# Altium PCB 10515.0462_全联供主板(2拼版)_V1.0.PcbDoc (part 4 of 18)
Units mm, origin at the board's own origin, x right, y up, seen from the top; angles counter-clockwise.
Board outline 282 x 198 mm, 2 copper layers (Top Layer, Bottom Layer); 716 components, 0 nets, 2364 pads, 1800 vias.
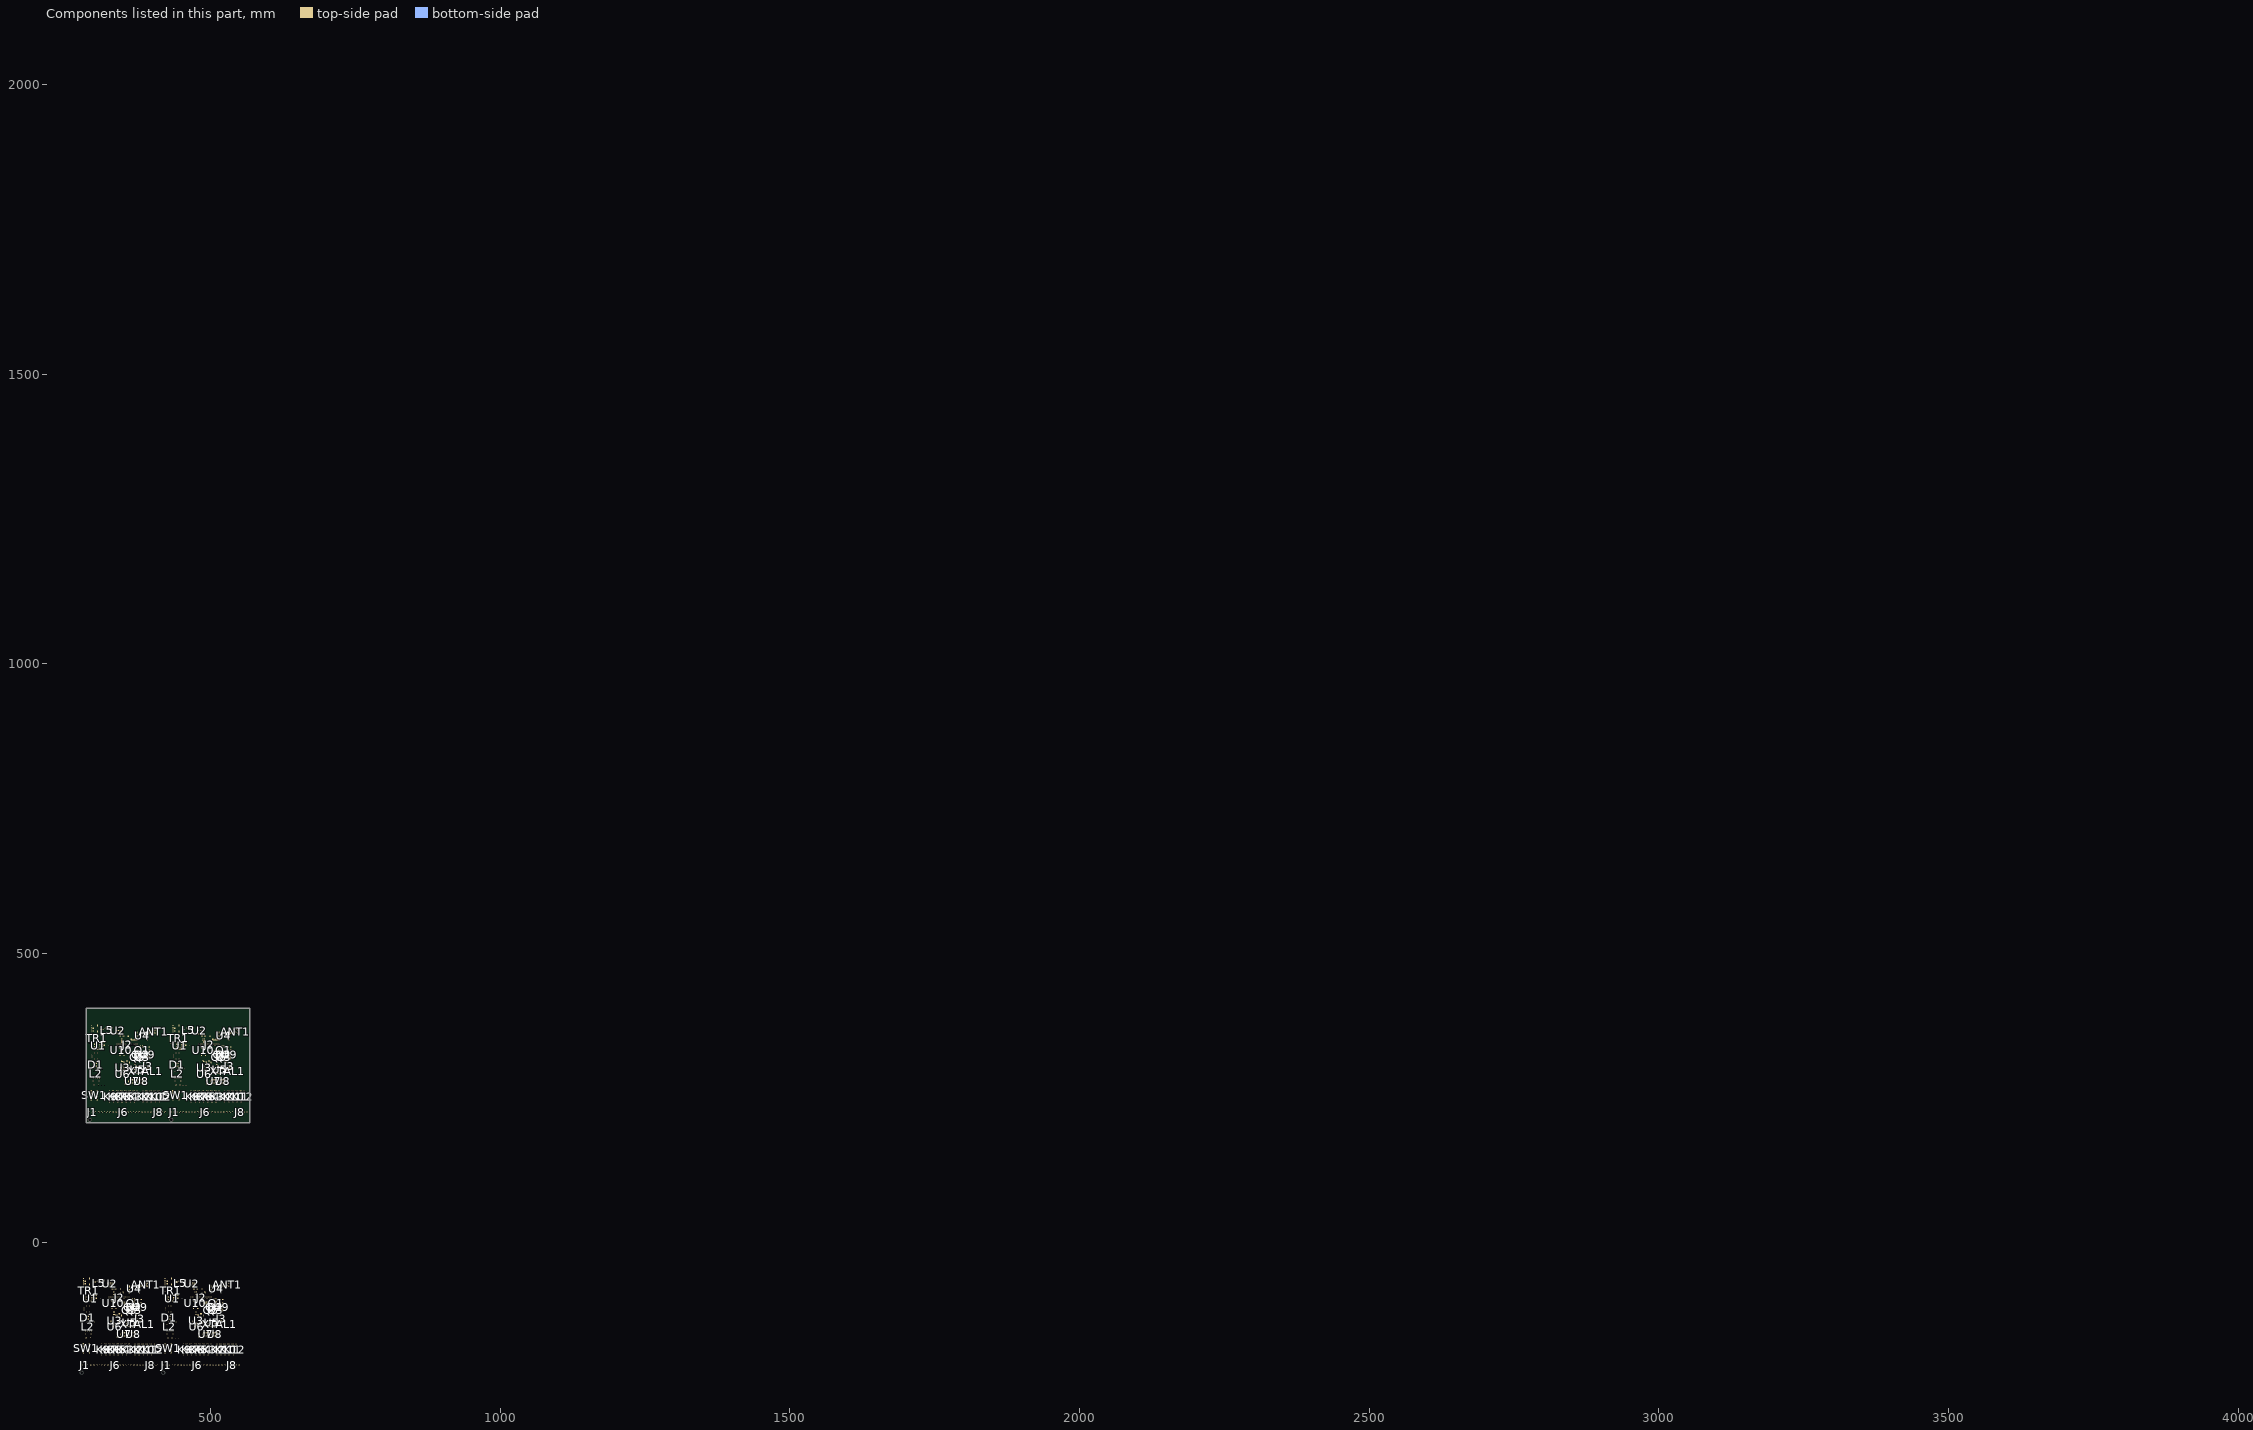
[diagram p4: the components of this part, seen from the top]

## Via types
v1: diameter 0.7, hole 0.4, Top Layer to Bottom Layer, tented both sides, 1800 vias

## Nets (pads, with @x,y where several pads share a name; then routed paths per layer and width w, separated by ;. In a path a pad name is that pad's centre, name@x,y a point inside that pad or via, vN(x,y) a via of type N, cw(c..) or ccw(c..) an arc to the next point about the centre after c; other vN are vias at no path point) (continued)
copper on no net: (continued)
  Top Layer w0.2: 384.544,295.781 ccw(c384.991,296.229) 384.991,295.596 ; 384.653,297.574 cw(c384.653,297.003) 385.057,297.407 ; 384.917,-74.482 385.033,-74.482 ; 385.228,311.309 cw(c384.705,310.786) 385.445,310.786 cw(c386.185,310.786) 385.662,311.309 ; 385.228,312.998 ccw(c384.705,312.475) 384.705,313.215 ccw(c384.705,313.955) 385.228,313.432 ; 385.297,295.69 cw(c385.792,295.69) 385.442,296.039 ; 385.437,322.933 cw(c384.697,322.194) 385.74,322.114 ; 385.629,320.162 cw(c385.106,319.639) 385.846,319.639 cw(c386.586,319.639) 386.063,320.162 ; 385.744,322.625 cw(c385.269,322.15) 385.939,322.099 ; 385.754,322.398 ccw(c385.714,322.523) 385.846,322.523 ccw(c385.978,322.523) 385.938,322.398 ; 386.411,301.303 387.841,301.303 ; 387.026,320.162 cw(c386.548,319.684) 387.224,319.684 ; 387.042,322.337 ccw(c386.66,322.777) 387.243,322.777 ccw(c387.826,322.777) 387.444,322.337 ; 387.224,319.594 cw(c388.028,319.594) 387.46,320.162 ; 387.587,301.086 ccw(c387.063,300.563) 387.063,301.303 ccw(c387.063,302.043) 387.587,301.52 ; 388.212,318.92 cw(c388.987,318.145) 389.077,319.238 ; 388.517,319.226 cw(c389.034,318.709) 389.094,319.437 ; 388.793,319.294 ccw(c388.674,319.258) 388.674,319.382 ; 388.793,319.471 cw(c388.674,319.507) 388.674,319.382 ; 388.819,295.758 ccw(c388.711,296.025) 388.999,296.025 ; v1@388.916,316.625 cw(c388.554,316.235) 389.086,316.235 ; 388.999,295.193 388.999,296.025 ; v1(389.086,316.808) 389.086,316.235 ; 389.086,319.382 388.673,319.382 ; 389.178,295.758 cw(c389.287,296.025) 388.999,296.025 ; v1@389.256,316.625 ccw(c389.618,316.235) 389.086,316.235 ; 389.53,301.341 389.492,301.303 391.277,301.303 ; 389.53,302.947 389.53,303.074 ; 389.656,348.23 cw(c392.417,348.23) 390.465,350.183 ; 389.656,348.713 cw(c391.935,348.713) 390.323,350.324 ; 389.656,349.196 cw(c391.452,349.196) 390.182,350.465 ; 389.656,349.678 cw(c390.969,349.678) 390.04,350.607 ; 389.747,301.086 cw(c390.27,300.563) 390.27,301.303 cw(c390.27,302.043) 389.747,301.52 ; 389.788,350.395 cw(c389.29,350.305) 389.648,349.948 cw(c389.986,349.609) 390.093,350.076 ; 389.833,352.27 ccw(c389.499,352.082) 389.499,352.465 ; 389.833,352.661 cw(c389.499,352.849) 389.499,352.465 ; 389.899,354.183 ccw(c389.216,353.5) 389.216,354.465 ccw(c389.216,355.431) 389.899,354.748 ; 389.899,356.183 ccw(c389.216,355.5) 389.216,356.465 ccw(c389.216,357.431) 389.899,356.748 ; 390.632,352.465 389.499,352.465 ; 390.632,354.465 389.213,354.465 388.767,354.019 388.767,347.288 388.132,346.653 352.572,346.653 352.11,346.191 352.11,345.175 ; 391.023,301.086 ccw(c390.499,300.563) 390.499,301.303 ccw(c390.499,302.043) 391.023,301.52 ; 391.312,302.838 391.312,302.897 391.312,303.024 ; 391.966,317.476 cw(c391.443,316.953) 392.183,316.953 cw(c392.923,316.953) 392.4,317.476 ; 392.183,317.731 392.183,316.415 391.815,316.046 389.275,316.046 389.086,316.235 ; 393.515,317.476 cw(c392.992,316.953) 393.731,316.953 cw(c394.471,316.953) 393.948,317.476 ; 394.558,303.251 ccw(c393.705,304.104) 394.912,304.104 ccw(c396.119,304.104) 395.265,303.251 ; 394.658,304.951 cw(c394.044,304.338) 394.912,304.338 ; 394.7,303.109 ccw(c394.188,303.621) 394.912,303.621 ccw(c395.636,303.621) 395.124,303.109 ; 394.912,303.024 394.912,305.078 ; 394.912,303.217 cw(c397.363,303.217) 395.63,304.951 ; 394.912,303.7 cw(c396.881,303.7) 395.488,305.092 ; 394.912,304.183 cw(c396.398,304.183) 395.347,305.234 ; 394.912,304.666 cw(c395.915,304.666) 395.206,305.375 ; 395.042,364.769 395.182,364.628 395.208,364.654 ; v1@396.046,362.114 v1@396.26,362.114 ; 398.546,362.114 398.661,362.114 ; 464.372,-67.652 464.436,-67.652 ; 464.712,-72.355 ccw(c464.616,-72.151) 464.841,-72.151 ; 464.801,-72.683 cw(c465.172,-72.444) 464.86,-72.132 ; 464.841,-72.632 464.841,-72.151 ; 464.969,-72.575 cw(c465.386,-72.307) 465.036,-71.957 ; 464.971,-72.355 cw(c465.066,-72.151) 464.841,-72.151 ; 465.137,-72.467 cw(c465.6,-72.17) 465.211,-71.781 ; 465.458,-70.292 466.105,-70.292 466.481,-70.668 466.481,-71.4 466.1,-71.781 465.211,-71.781 ; 465.458,-68.992 466.095,-68.992 ; 465.858,-70.392 cw(c465.858,-71.23) 466.451,-70.638 ; 465.858,-70.192 cw(c465.858,-70.547) 466.109,-70.296 ; 465.891,-68.898 ccw(c466.015,-68.549) 466.276,-68.811 ; 465.91,-70.378 cw(c466.045,-70.599) 466.229,-70.416 ; 465.929,-70.363 cw(c466.099,-70.534) 466.099,-70.292 cw(c466.099,-70.051) 465.929,-70.222 ; 465.93,-69.062 cw(c466.095,-69.223) 466.095,-68.992 ; 465.93,-68.922 ccw(c466.095,-68.762) 466.095,-68.992 ; 466.06,-67.869 cw(c465.537,-68.392) 466.277,-68.392 cw(c467.016,-68.392) 466.493,-67.869 ; 466.277,-67.652 466.277,-68.811 ; v1@467.024,-70.292 468.204,-70.292 ; v1@467.166,-70.434 cw(c467.508,-70.776) 467.508,-70.292 ; v1@467.166,-70.08 ccw(c467.678,-69.568) 467.678,-70.292 ; 467.239,-68.483 ccw(c466.408,-67.652) 467.583,-67.652 ; 467.58,-68.142 ccw(c467.09,-67.652) 467.783,-67.652 ; 467.674,-68.048 cw(c467.889,-68.263) 467.889,-67.959 ; 467.733,-70.363 ccw(c467.563,-70.534) 467.563,-70.292 ccw(c467.563,-70.051) 467.733,-70.222 ; 467.733,-69.713 ccw(c467.563,-69.884) 467.563,-69.642 ccw(c467.563,-69.401) 467.733,-69.572 ; 467.928,-67.652 467.928,-67.795 467.116,-68.606 467.116,-69.368 467.39,-69.642 468.204,-69.642 469.503,-69.642 470.519,-70.658 ; 468.243,-136.468 468.274,-136.499 ; 468.675,-69.713 cw(c468.845,-69.884) 468.845,-69.642 cw(c468.845,-69.401) 468.675,-69.572 ; 469.786,-134.848 469.817,-134.848 469.892,-134.923 ; 469.817,-136.499 470.123,-136.193 ; 469.974,-70.112 cw(c469.367,-70.718) 470.225,-70.718 ; 470.091,-70.23 ccw(c470.531,-69.79) 470.531,-70.412 ; 470.277,-68.852 470.412,-68.987 470.531,-69.106 ; 478,368.943 478.065,368.943 ; 478.34,364.241 ccw(c478.245,364.445) 478.47,364.445 ; 478.43,363.913 cw(c478.801,364.151) 478.489,364.463 ; 478.46,-146.854 483.91,-146.854 484.314,-146.449 484.314,-140.308 484.601,-140.021 490.899,-140.021 ; 478.46,-145.584 483.402,-145.584 483.914,-145.071 483.914,-142.393 ; 478.47,363.963 478.47,364.445 ; 478.598,364.021 cw(c479.015,364.289) 478.664,364.639 ; 478.6,364.241 cw(c478.695,364.445) 478.47,364.445 ; 478.766,364.129 cw(c479.228,364.426) 478.84,364.814 ; 479.087,366.303 479.734,366.303 480.11,365.927 480.11,365.195 479.729,364.814 478.84,364.814 478.47,364.445 ; 479.087,367.603 479.724,367.603 ; 479.481,-91.369 479.481,-91.42 ; 479.487,366.203 cw(c479.487,365.365) 480.079,365.958 ; 479.487,366.403 cw(c479.487,366.048) 479.738,366.299 ; 479.52,367.698 ccw(c479.643,368.047) 479.905,367.785 ; 479.539,366.218 cw(c479.674,365.996) 479.857,366.18 ; 479.557,366.233 cw(c479.728,366.062) 479.728,366.303 cw(c479.728,366.545) 479.557,366.374 ; 479.558,367.534 cw(c479.724,367.373) 479.724,367.603 ; 479.558,367.673 ccw(c479.724,367.834) 479.724,367.603 ; 479.57,-146.998 cw(c479.919,-147.348) 479.919,-146.854 cw(c479.919,-146.359) 479.57,-146.709 ; 479.57,-145.728 cw(c479.919,-146.078) 479.919,-145.584 cw(c479.919,-145.089) 479.57,-145.439 ; 479.689,368.727 cw(c479.166,368.204) 479.905,368.204 cw(c480.645,368.204) 480.122,368.727 ; 479.905,368.943 479.905,367.785 ; v1@480.075,-108.463 ccw(c479.621,-108.425) 479.943,-108.103 ; 480.128,-93.967 cw(c480.738,-94.576) 480.805,-93.717 ; v1@480.303,-108.235 cw(c480.265,-107.781) 479.943,-108.103 ; 480.31,-93.785 ccw(c480.043,-93.517) 480.421,-93.517 ; v1(480.324,-108.484) 479.943,-108.103 ; 480.538,-96.34 cw(c479.252,-97.627) 481.071,-97.627 ; v1@480.653,366.303 481.833,366.303 ; 480.68,-96.199 cw(c479.734,-97.144) 481.071,-97.144 ; v1@480.795,366.162 cw(c481.136,365.82) 481.136,366.303 ; v1@480.795,366.515 ccw(c481.306,367.027) 481.306,366.303 ; 480.821,-96.057 cw(c480.217,-96.661) 481.071,-96.661 ; 480.821,-95.795 481.071,-96.046 481.071,-108.469 481.428,-108.825 492.314,-108.825 492.903,-109.414 492.903,-126.264 492.914,-126.264 493.278,-126.629 498.609,-126.629 499.272,-127.291 499.272,-131.621 ; 480.821,-93.255 480.821,-93.274 479.943,-94.152 479.943,-108.103 ; 480.867,368.112 ccw(c480.036,368.943) 481.212,368.943 ; 480.918,-134.923 480.993,-134.848 ; 481.209,368.454 ccw(c480.719,368.943) 481.412,368.943 ; 481.303,368.548 cw(c481.518,368.333) 481.518,368.637 ; 481.362,366.233 ccw(c481.191,366.062) 481.191,366.303 ccw(c481.191,366.545) 481.362,366.374 ; 481.362,366.883 ccw(c481.191,366.712) 481.191,366.953 ccw(c481.191,367.195) 481.362,367.024 ; v1@481.544,-107.545 ccw(c481.118,-107.118) 481.721,-107.118 ccw(c482.325,-107.118) v1@481.898,-107.545 ; 481.556,368.943 481.556,368.801 480.745,367.989 480.745,367.227 481.019,366.953 481.833,366.953 483.132,366.953 484.148,365.938 ; v1(481.721,-110.389) 481.721,-110.77 ; v1(481.721,-107.722) 481.721,-90.958 482.337,-90.342 515.865,-90.342 516.538,-89.669 516.538,-84.462 516.87,-84.13 ; 481.872,300.128 481.903,300.097 ; 482.303,366.883 cw(c482.474,366.712) 482.474,366.953 cw(c482.474,367.195) 482.303,367.024 ; v1@482.36,-107.214 ccw(c481.757,-107.214) 482.183,-106.787 ccw(c482.61,-106.36) v1@482.61,-106.964 ; v1(482.61,-107.214) 482.121,-106.725 482.121,-92.101 482.121,-91.339 482.718,-90.742 516.354,-90.742 517.027,-90.069 517.027,-86.64 517.537,-86.13 518.003,-86.13 ; v1(482.737,-110.389) 482.864,-110.262 491.269,-110.262 491.703,-110.697 491.703,-132.646 491.701,-132.648 491.701,-133.85 491.703,-133.852 491.703,-134.573 492.152,-135.021 495.372,-135.021 ; v1@482.772,-110.424 cw(c483.164,-110.816) 483.164,-110.262 ; v1@482.914,-110.566 cw(c483.647,-111.299) 483.647,-110.262 ; 483.078,-96.34 cw(c482.395,-97.023) 483.361,-97.023 cw(c484.327,-97.023) 483.644,-96.34 ; v1@483.122,-91.593 cw(c482.519,-91.593) 482.945,-92.02 cw(c483.372,-92.447) v1@483.372,-91.843 ; v1@483.195,-107.545 ccw(c482.769,-107.118) 483.372,-107.118 ccw(c483.976,-107.118) v1@483.549,-107.545 ; 483.361,-95.795 483.361,-106.314 484.022,-106.975 484.022,-107.864 484.584,-108.425 492.966,-108.425 493.303,-108.763 493.303,-125.756 493.684,-126.137 498.999,-126.137 499.772,-126.91 499.772,-131.621 ; 483.361,-93.255 484.161,-94.055 484.161,-106.467 484.422,-106.728 484.422,-107.698 484.749,-108.025 493.131,-108.025 493.703,-108.597 493.703,-125.292 494.04,-125.629 499.499,-125.629 500.272,-126.402 500.272,-131.621 ; v1(483.372,-107.722) 483.372,-106.96 482.521,-106.109 482.521,-92.444 v1(483.372,-91.593) ; 483.395,-93.715 cw(c483.515,-94.417) 484.019,-93.913 ; 483.415,301.748 483.446,301.748 483.52,301.673 ; 483.446,300.097 483.752,300.403 ; 483.602,366.483 cw(c482.996,365.877) 483.853,365.877 ; 483.72,366.366 ccw(c484.16,366.806) 484.16,366.183 ; v1@483.753,-112.036 cw(c483.753,-112.64) 484.18,-112.213 cw(c484.607,-111.786) v1@484.003,-111.786 ; v1(483.753,-111.786) 484.403,-112.436 485.658,-112.436 485.908,-112.186 490.249,-112.186 490.503,-112.44 490.503,-132.149 490.501,-132.151 490.501,-134.347 490.503,-134.349 490.503,-135.139 491.886,-136.521 495.372,-136.521 ; 483.761,-93.517 ccw(c484.094,-93.517) 483.859,-93.753 ; 483.906,367.744 484.041,367.608 484.16,367.49 ; 483.914,-141.134 483.914,-142.393 ; v1@484.465,-92.278 cw(c484.039,-92.705) 484.642,-92.705 cw(c485.246,-92.705) v1@484.819,-92.278 ; v1(484.642,-92.101) 484.642,-106.383 485.101,-106.842 ; v1@484.973,-107.164 ccw(c484.665,-106.856) 485.101,-106.856 ; v1(485.023,-111.786) 490.738,-111.786 490.903,-111.951 490.903,-132.315 490.901,-132.317 490.901,-134.181 490.903,-134.183 490.903,-134.973 491.951,-136.021 495.372,-136.021 ; v1(485.15,-107.341) 485.101,-107.292 485.101,-106.842 ; v1@485.2,-111.963 cw(c485.627,-112.39) 485.627,-111.786 cw(c485.627,-111.182) v1@485.2,-111.609 ; 485.212,-93.944 cw(c485.778,-94.51) 485.876,-93.716 ; v1@485.268,-107.121 cw(c485.417,-106.842) 485.101,-106.842 ; 485.403,-93.753 ccw(c485.168,-93.517) 485.501,-93.517 ; 485.617,-136.435 485.642,-136.461 ; 485.618,-96.34 cw(c484.935,-97.023) 485.901,-97.023 cw(c486.867,-97.023) 486.184,-96.34 ; 485.901,-95.795 485.901,-106.441 486.686,-107.225 494.179,-107.225 494.503,-107.55 494.503,-124.403 494.929,-124.829 500.461,-124.829 501.272,-125.64 501.272,-131.621 ; 485.901,-93.255 485.054,-94.103 485.054,-106.228 486.451,-107.625 493.69,-107.625 494.103,-108.039 494.103,-124.911 494.421,-125.229 499.98,-125.229 500.772,-126.021 500.772,-131.621 ; v1@486.293,-112.929 v1(486.547,-112.929) 489.468,-112.929 490.103,-113.564 490.103,-131.984 490.101,-131.986 490.101,-134.512 490.103,-134.514 490.103,-135.386 491.739,-137.021 495.372,-137.021 ; v1@486.678,-106.452 ccw(c486.075,-106.452) 486.501,-106.025 ccw(c486.928,-105.598) v1@486.928,-106.202 ; v1@486.724,-113.106 cw(c487.151,-113.533) 487.151,-112.929 cw(c487.151,-112.325) v1@486.724,-112.752 ; v1@486.751,-92.278 cw(c486.325,-92.705) 486.928,-92.705 cw(c487.532,-92.705) v1@487.105,-92.278 ; v1(486.928,-106.452) 486.42,-105.944 486.42,-97.17 486.928,-96.662 v1(486.928,-92.101) ; 487.102,-136.461 487.127,-136.461 ; 487.187,-138.115 cw(c486.504,-138.798) 487.47,-138.798 cw(c488.436,-138.798) 487.753,-138.115 ; 487.47,-137.832 487.47,-138.848 487.654,-139.032 495.361,-139.032 495.372,-139.021 ; 488.436,-153.924 ccw(c488.009,-153.497) 488.613,-153.497 ccw(c489.217,-153.497) 488.79,-153.924 ; 488.507,-136.097 488.833,-136.424 490.507,-136.424 491.604,-137.521 495.372,-137.521 ; 488.613,-154.85 488.613,-150.278 489.267,-149.624 497.757,-149.624 498.272,-149.109 498.272,-143.921 ; 488.897,-105.537 cw(c488.374,-106.06) 489.114,-106.06 cw(c489.854,-106.06) 489.331,-105.537 ; 488.994,-137.832 488.994,-138.285 489.341,-138.632 494.118,-138.632 494.229,-138.521 495.372,-138.521 ; 489.058,-136.652 cw(c489.609,-137.203) 489.609,-136.424 ; 489.058,-136.219 ccw(c489.554,-135.723) 489.554,-136.424 ; 489.114,-105.32 489.114,-106.471 489.468,-106.825 494.515,-106.825 494.903,-107.214 494.903,-124.105 495.227,-124.429 501.069,-124.429 501.772,-125.132 501.772,-131.621 ; 489.114,-103.669 v1@489.756,-103.669 ; 489.399,-103.85 cw(c489.756,-104.111) v1@489.756,-103.669 ; 489.399,-103.489 ccw(c489.756,-103.228) v1@489.756,-103.669 ; 489.706,-153.924 ccw(c489.279,-153.497) 489.883,-153.497 ccw(c490.487,-153.497) 490.06,-153.924 ; v1@489.706,-103.846 ccw(c489.279,-104.273) 489.279,-103.669 ccw(c489.279,-103.066) v1@489.706,-103.493 ; 489.883,-154.85 489.883,-150.786 490.645,-150.024 498.138,-150.024 498.772,-149.39 498.772,-143.921 ; 490.682,-141.238 ccw(c490.159,-140.715) 490.899,-140.715 ccw(c491.639,-140.715) 491.116,-141.238 ; 490.707,-138.021 495.372,-138.021 ; 490.899,-141.492 490.899,-140.021 ; 490.976,-153.924 ccw(c490.549,-153.497) 491.153,-153.497 ccw(c491.757,-153.497) 491.33,-153.924 ; 491.153,-154.85 491.153,-151.167 491.845,-150.475 498.703,-150.475 499.272,-149.906 499.272,-143.921 ; 492.089,289.742 497.539,289.742 497.943,290.146 497.943,296.287 498.229,296.574 504.528,296.574 ; 492.089,291.012 497.031,291.012 497.543,291.524 497.543,294.202 ; 492.246,-153.924 ccw(c491.819,-153.497) 492.423,-153.497 ccw(c493.027,-153.497) 492.6,-153.924 ; 492.423,-154.85 492.423,-151.421 492.969,-150.875 499.192,-150.875 499.772,-150.295 499.772,-143.921 ; 492.46,-105.537 cw(c491.937,-106.06) 492.677,-106.06 cw(c493.417,-106.06) 492.894,-105.537 ; 492.632,-101.941 v1@493.262,-101.941 ; 492.657,-141.49 492.727,-141.49 ; 492.677,-105.32 492.677,-106.078 493.024,-106.425 495.03,-106.425 495.303,-106.699 495.303,-123.724 495.303,-123.768 495.564,-124.029 501.55,-124.029 502.272,-124.751 502.272,-131.621 ; 492.677,-103.669 v1(493.439,-103.669) ; 492.727,-143.141 493.464,-143.141 ; 492.92,-102.118 cw(c493.262,-102.36) v1@493.262,-101.941 ; 492.92,-101.765 ccw(c493.262,-101.523) v1@493.262,-101.941 ; 492.935,-103.883 cw(c493.439,-104.371) v1(493.439,-103.669) ; 492.935,-103.456 ccw(c493.439,-102.968) v1(493.439,-103.669) ; 492.944,-143.357 cw(c493.464,-143.875) 493.464,-143.141 ; 492.944,-142.925 ccw(c493.464,-142.407) 493.464,-143.141 ; 493.11,345.226 493.11,345.175 ; 493.199,289.597 cw(c493.548,289.247) 493.548,289.742 cw(c493.548,290.236) 493.199,289.887 ; 493.199,290.867 cw(c493.548,290.517) 493.548,291.012 cw(c493.548,291.506) 493.199,291.157 ; v1@493.212,-102.118 ccw(c492.785,-102.545) 492.785,-101.941 ccw(c492.785,-101.338) v1@493.212,-101.765 ; v1@493.262,-103.846 ccw(c492.835,-104.273) 492.835,-103.669 ccw(c492.835,-103.066) v1@493.262,-103.493 ; 493.516,-153.924 ccw(c493.089,-153.497) 493.693,-153.497 ccw(c494.297,-153.497) 493.87,-153.924 ; 493.521,-93.917 cw(c493.521,-95.516) 494.651,-94.386 cw(c495.781,-93.255) 494.183,-93.255 ; 493.521,-93.717 cw(c493.521,-94.833) 494.31,-94.044 cw(c495.098,-93.255) 493.983,-93.255 ; 493.521,-93.255 494.802,-94.537 494.802,-98.324 495.075,-98.597 498.485,-98.597 498.823,-98.935 498.823,-99.805 499.12,-100.102 512.328,-100.102 512.709,-100.483 512.709,-113.564 513.217,-114.072 ; 493.693,-154.85 493.693,-151.929 494.347,-151.275 499.554,-151.275 500.272,-150.557 500.272,-143.921 ; v1@493.704,328.132 ccw(c493.25,328.17) 493.572,328.492 ccw(c493.894,328.815) v1@493.932,328.361 ; 493.757,342.629 cw(c494.367,342.019) 494.434,342.879 ; v1@493.786,-81.56 496.834,-81.56 497.45,-81.56 497.704,-81.306 497.704,-72.784 498.358,-72.13 500.303,-72.13 ; v1@493.913,-141.021 495.372,-141.021 ; 493.939,342.811 ccw(c493.672,343.078) 494.05,343.078 ; v1(493.953,328.111) 493.572,328.492 493.572,342.443 494.45,343.321 494.45,343.34 ; 494.167,340.255 cw(c492.88,338.969) 494.7,338.969 ; v1(494.294,-82.322) 494.548,-82.068 496.58,-82.068 497.85,-82.068 498.104,-81.814 498.104,-81.179 498.104,-74.575 498.549,-74.13 500.303,-74.13 ; 494.308,340.397 cw(c493.363,339.451) 494.7,339.451 ; 494.389,-141.663 cw(c494.707,-141.981) 494.707,-141.531 ; 494.443,-141.61 cw(c494.646,-141.813) 494.705,-141.531 ; 494.45,340.538 cw(c493.846,339.934) 494.7,339.934 ; 494.45,340.8 494.7,340.55 494.7,328.126 495.056,327.77 505.943,327.77 506.532,327.181 506.532,310.331 506.542,310.331 506.907,309.967 512.238,309.967 512.901,309.304 512.901,304.974 ; 494.547,301.673 494.622,301.748 ; 494.786,-153.924 ccw(c494.359,-153.497) 494.963,-153.497 ccw(c495.567,-153.497) 495.14,-153.924 ; v1@494.929,-82.957 497.469,-82.957 498.358,-82.957 498.612,-82.703 498.612,-80.384 498.866,-80.13 ; 494.963,-154.85 494.963,-152.183 495.471,-151.675 500.043,-151.675 500.772,-150.946 500.772,-143.921 ; v1@495.106,-83.134 cw(c495.533,-83.561) 495.533,-82.957 cw(c495.533,-82.353) v1@495.106,-82.78 ; v1@495.173,329.05 ccw(c494.746,329.477) 495.35,329.477 ccw(c495.953,329.477) v1@495.527,329.05 ; v1(495.35,326.206) 495.35,325.825 ; v1(495.35,328.873) 495.35,345.637 495.966,346.253 529.494,346.253 530.167,346.926 530.167,352.133 530.499,352.465 ; 495.372,-141.521 494.531,-141.521 493.82,-142.232 493.82,-142.785 493.464,-143.141 ; 495.372,-140.521 504.768,-140.521 505.055,-140.234 505.055,-133.41 505.993,-132.472 506.979,-132.472 v1(507.629,-133.122) ; 495.372,-140.021 490.899,-140.021 ; 495.372,-139.521 484.212,-139.521 483.914,-139.819 483.914,-142.393 ; 495.372,-135.521 492.017,-135.521 491.303,-134.808 491.303,-134.017 491.301,-134.015 491.301,-132.483 491.303,-132.481 491.303,-111.211 491.117,-111.024 483.021,-111.024 483.006,-111.039 481.99,-111.039 481.721,-110.77 ; 495.372,-134.521 492.414,-134.521 492.103,-134.211 492.103,-133.686 492.101,-133.684 492.101,-132.814 492.103,-132.812 492.103,-110.322 491.407,-109.625 479.63,-109.625 479.081,-109.077 479.081,-89.915 479.562,-89.434 515.122,-89.434 515.63,-88.926 515.63,-80.798 516.298,-80.13 518.003,-80.13 ; 495.372,-134.021 492.781,-134.021 492.503,-133.744 492.503,-133.52 492.501,-133.518 492.501,-132.98 492.503,-132.978 492.503,-109.814 491.915,-109.225 479.796,-109.225 479.481,-108.911 479.481,-91.42 ; 495.593,-96.264 cw(c494.463,-97.394) 496.061,-97.394 cw(c497.659,-97.394) 496.529,-96.264 ; 495.734,-96.122 cw(c494.946,-96.911) 496.061,-96.911 cw(c497.176,-96.911) 496.388,-96.122 ; 495.882,-105.537 cw(c495.359,-106.06) 496.099,-106.06 cw(c496.839,-106.06) 496.316,-105.537 ; 495.915,-129.971 cw(c495.392,-130.494) 496.131,-130.494 cw(c496.871,-130.494) 496.348,-129.971 ; v1@495.989,329.381 ccw(c495.385,329.381) 495.812,329.808 ccw(c496.239,330.235) v1@496.239,329.631 ; 496.056,-153.924 ccw(c495.629,-153.497) 496.233,-153.497 ccw(c496.837,-153.497) 496.41,-153.924 ; 496.061,-95.795 496.061,-97.932 496.326,-98.197 498.745,-98.197 499.227,-98.679 499.227,-99.428 499.501,-99.702 512.69,-99.702 513.109,-100.121 513.109,-100.864 513.109,-113.202 513.344,-113.437 514.233,-113.437 514.614,-113.818 ; 496.061,-93.917 cw(c496.061,-95.516) 497.191,-94.386 cw(c498.321,-93.255) 496.723,-93.255 ; 496.061,-93.717 cw(c496.061,-94.833) 496.85,-94.044 cw(c497.638,-93.255) 496.523,-93.255 ; 496.061,-93.255 497.215,-94.41 497.215,-97.543 497.469,-97.797 498.911,-97.797 499.311,-98.197 505.871,-98.197 ; 496.099,-105.32 496.099,-106.298 495.703,-106.694 495.703,-123.216 495.703,-123.26 496.072,-123.629 501.819,-123.629 502.772,-124.582 502.772,-131.621 ; 496.099,-103.669 496.443,-103.669 496.106,-103.669 ; 496.131,-129.754 496.131,-130.514 496.453,-130.836 497.596,-130.836 ; 496.233,-154.85 496.233,-152.818 496.868,-152.183 500.297,-152.183 501.272,-151.208 501.272,-143.921 ; v1(496.239,329.381) 495.75,329.87 495.75,344.494 495.75,345.256 496.347,345.853 529.983,345.853 530.656,346.526 530.656,349.955 531.166,350.465 531.632,350.465 ; 496.324,-114.27 ccw(c495.778,-113.724) 496.551,-113.724 ; 496.334,-112.96 cw(c495.811,-113.483) 496.551,-113.483 cw(c497.29,-113.483) 496.767,-112.96 ; v1(496.366,326.206) 496.493,326.333 504.897,326.333 505.332,325.899 505.332,303.949 505.33,303.947 505.33,302.746 505.332,302.744 505.332,302.023 505.781,301.574 509.001,301.574 ; v1@496.401,326.171 cw(c496.793,325.779) 496.793,326.333 ; v1@496.543,326.03 cw(c497.276,325.296) 497.276,326.333 ; 496.551,-114.439 496.551,-112.743 ; 496.551,-113.77 ccw(c497.258,-113.77) 496.758,-114.27 ; 496.707,340.255 cw(c496.024,339.572) 496.99,339.572 cw(c497.955,339.572) 497.273,340.255 ; v1@496.751,345.002 cw(c496.147,345.002) 496.574,344.576 cw(c497.001,344.149) v1@497.001,344.752 ; v1@496.824,329.05 ccw(c496.397,329.477) 497.001,329.477 ccw(c497.604,329.477) v1@497.178,329.05 ; 496.99,340.8 496.99,330.282 497.651,329.62 497.651,328.731 498.212,328.17 506.594,328.17 506.932,327.832 506.932,310.839 507.313,310.458 512.627,310.458 513.401,309.685 513.401,304.974 ; 496.99,343.34 497.79,342.54 497.79,330.128 498.051,329.867 498.051,328.897 498.378,328.57 506.76,328.57 507.332,327.998 507.332,311.303 507.669,310.966 513.127,310.966 513.901,310.193 513.901,304.974 ; v1(497.001,328.873) 497.001,329.635 496.15,330.486 496.15,344.151 v1(497.001,345.002) ; 497.024,342.881 cw(c497.144,342.179) 497.647,342.682 ; v1@497.382,324.559 cw(c497.382,323.956) 497.809,324.383 cw(c498.235,324.809) v1@497.632,324.809 ; v1(497.382,324.809) 498.032,324.159 499.287,324.159 499.537,324.409 503.878,324.409 504.132,324.155 504.132,304.446 504.13,304.444 504.13,302.249 504.132,302.247 504.132,301.457 505.514,300.074 509.001,300.074 ; 497.39,343.078 ccw(c497.723,343.078) 497.487,342.842 ; 497.457,-130.836 cw(c497.457,-131.271) 497.765,-130.963 ; 497.543,295.461 497.543,294.202 ; 497.66,-130.9 ccw(c497.772,-130.788) 497.772,-130.946 ; 497.762,-130.959 ccw(c497.596,-131.01) 497.596,-130.836 ; 497.772,-143.921 497.772,-141.963 498.104,-141.631 504.835,-141.631 505.455,-141.011 505.455,-133.645 505.978,-133.122 v1(506.613,-133.122) ; 497.772,-131.621 497.772,-131.012 497.596,-130.836 ; 497.782,-129.754 498.272,-130.244 498.272,-131.621 ; 497.833,-130.061 cw(c497.855,-130.623) 498.253,-130.225 cw(c498.587,-129.891) 498.122,-129.808 ; 497.985,-116.474 cw(c497.462,-116.997) 498.202,-116.997 cw(c498.941,-116.997) 498.418,-116.474 ; v1@498.094,344.318 cw(c497.667,343.891) 498.271,343.891 cw(c498.874,343.891) v1@498.448,344.318 ; 498.202,-116.257 498.202,-120.243 498.202,-122.818 498.599,-123.216 502.93,-123.216 503.272,-123.558 503.272,-131.621 ; v1(498.271,344.494) 498.271,330.213 498.73,329.754 ; 498.601,-95.795 498.601,-96.916 498.866,-97.181 502.422,-97.181 503.946,-95.657 505.871,-95.657 ; 498.601,-93.917 cw(c498.601,-95.516) 499.731,-94.386 cw(c500.861,-93.255) 499.263,-93.255 ; 498.601,-93.717 cw(c498.601,-94.833) 499.39,-94.044 cw(c500.178,-93.255) 499.063,-93.255 ; 498.601,-93.255 499.86,-94.514 501.857,-94.514 502.619,-93.752 524.52,-93.752 525.047,-94.279 525.047,-144.533 524.412,-145.168 511.224,-145.168 510.692,-144.636 510.692,-141.115 510.098,-140.521 507.672,-140.521 ; v1@498.602,329.431 ccw(c498.294,329.739) 498.73,329.739 ; v1(498.652,324.809) 504.367,324.809 504.532,324.644 504.532,304.28 504.53,304.278 504.53,302.415 504.532,302.413 504.532,301.622 505.58,300.574 509.001,300.574 ; v1(498.779,329.254) 498.73,329.304 498.73,329.754 ; v1@498.829,324.633 cw(c499.255,324.206) 499.255,324.809 cw(c499.255,325.413) v1@498.829,324.986 ; 498.841,342.651 cw(c499.407,342.085) 499.505,342.88 ; v1@498.897,329.475 cw(c499.046,329.754) 498.73,329.754 ; 499.032,342.842 ccw(c498.797,343.078) 499.13,343.078 ; 499.245,300.16 499.271,300.135 ; 499.247,340.255 cw(c498.564,339.572) 499.53,339.572 cw(c500.495,339.572) 499.813,340.255 ; 499.53,340.8 499.53,330.155 500.314,329.37 507.807,329.37 508.132,329.045 508.132,312.192 508.558,311.766 514.089,311.766 514.901,310.955 514.901,304.974 ; 499.53,343.34 498.682,342.493 498.682,330.367 500.079,328.97 507.318,328.97 507.732,328.556 507.732,311.684 508.05,311.366 513.608,311.366 514.401,310.574 514.401,304.974 ; 499.57,-80.413 ccw(c498.887,-81.096) 498.887,-80.13 ; 499.57,-79.847 cw(c498.887,-79.164) 498.887,-80.13 ; 499.57,-74.413 ccw(c498.887,-75.096) 498.887,-74.13 ccw(c498.887,-73.164) 499.57,-73.847 ; 499.57,-72.413 ccw(c498.887,-73.096) 498.887,-72.13 ccw(c498.887,-71.164) 499.57,-71.847 ; 499.89,-119.126 cw(c499.367,-119.649) 500.107,-119.649 cw(c500.846,-119.649) 500.323,-119.126 ; v1@499.922,323.666 v1(500.176,323.666) 503.097,323.666 503.732,323.031 503.732,304.612 503.73,304.61 503.73,302.083 503.732,302.081 503.732,301.21 505.368,299.574 509.001,299.574 ; 500.107,-118.909 500.107,-121.154 500.263,-121.311 507.629,-121.311 507.968,-121.65 507.968,-131.177 507.524,-131.621 505.272,-131.621 ; 500.303,-80.13 498.887,-80.13 ; v1@500.307,330.143 ccw(c499.703,330.143) 500.13,330.57 ccw(c500.557,330.997) v1@500.557,330.393 ; v1@500.353,323.49 cw(c500.779,323.063) 500.779,323.666 cw(c500.779,324.27) v1@500.353,323.843 ; v1@500.38,344.318 cw(c499.953,343.891) 500.557,343.891 cw(c501.16,343.891) v1@500.734,344.318 ; v1(500.557,330.143) 500.049,330.651 500.049,339.426 500.557,339.934 v1(500.557,344.494) ; 500.73,300.135 500.756,300.135 ; 500.816,298.48 cw(c500.133,297.797) 501.099,297.797 cw(c502.064,297.797) 501.382,298.48 ; 501.099,298.763 501.099,297.747 501.283,297.563 508.99,297.563 509.001,297.574 ; 501.141,-93.255 525.04,-93.255 525.447,-93.663 525.447,-144.768 524.647,-145.568 511.058,-145.568 510.203,-144.713 510.203,-141.388 509.836,-141.021 507.672,-141.021 ; 501.313,-95.623 501.141,-95.795 502.784,-94.152 524.158,-94.152 524.647,-94.641 524.647,-144.367 524.246,-144.768 511.389,-144.768 511.092,-144.471 511.092,-140.753 510.36,-140.021 507.672,-140.021 ; 501.468,-93.582 cw(c502.256,-94.371) 502.256,-93.255 cw(c502.256,-92.14) 501.468,-92.929 ; 501.609,-93.724 cw(c502.739,-94.854) 502.739,-93.255 cw(c502.739,-91.657) 501.609,-92.787 ; 501.758,-109.765 501.782,-109.79 ; 501.772,-143.921 501.772,-151.649 502.587,-152.464 503.753,-152.464 503.98,-152.691 503.98,-154.85 ; 501.78,-114.423 501.948,-114.591 ; 501.78,-112.803 501.782,-112.801 ; 502.065,282.672 ccw(c501.638,283.099) 502.242,283.099 ccw(c502.845,283.099) 502.419,282.672 ; 502.135,300.498 502.462,300.171 504.135,300.171 505.233,299.074 509.001,299.074 ; 502.242,281.745 502.242,286.317 502.896,286.971 511.386,286.971 511.901,287.486 511.901,292.674 ; 502.272,-143.921 502.272,-151.387 502.949,-152.064 504.877,-152.064 505.25,-152.437 505.25,-154.85 ; 502.526,331.058 cw(c502.003,330.535) 502.743,330.535 cw(c503.483,330.535) 502.96,331.058 ; 502.623,298.763 502.623,298.31 502.97,297.963 507.746,297.963 507.857,298.074 509.001,298.074 ; 502.687,299.943 cw(c503.238,299.393) 503.238,300.171 ; 502.687,300.377 ccw(c503.183,300.872) 503.183,300.171 ; 502.743,331.275 502.743,330.124 503.097,329.77 508.143,329.77 508.532,329.381 508.532,312.49 508.856,312.166 514.697,312.166 515.401,311.463 515.401,304.974 ; 502.743,332.926 v1@503.385,332.926 ; 502.772,-143.921 502.772,-150.998 503.438,-151.664 506.255,-151.664 506.52,-151.929 506.52,-154.85 ; 503.028,332.745 cw(c503.385,332.484) v1@503.385,332.926 ; 503.028,333.107 ccw(c503.385,333.368) v1@503.385,332.926 ; 503.272,-143.921 503.272,-147.357 503.853,-147.938 503.853,-148.31 ; 503.335,282.672 ccw(c502.908,283.099) 503.512,283.099 ccw(c504.115,283.099) 503.689,282.672 ; v1@503.335,332.749 ccw(c502.908,332.323) 502.908,332.926 ccw(c502.908,333.53) v1@503.335,333.103 ; 503.443,-147.528 cw(c502.709,-148.262) 503.747,-148.271 ; v1@503.502,-122.25 cw(c502.851,-122.901) 503.772,-122.901 ; 503.512,281.745 503.512,285.809 504.274,286.571 511.767,286.571 512.401,287.205 512.401,292.674 ; v1@503.644,-122.108 cw(c503.334,-122.418) 503.772,-122.418 ; 503.772,-143.921 503.772,-147.149 504.107,-147.484 504.869,-147.484 505.123,-147.738 505.123,-150.856 505.377,-151.11 507.479,-151.11 507.79,-151.421 507.79,-154.85 ; 503.772,-131.621 v1@503.772,-122.166 ; 503.772,-122.452 cw(c504.058,-122.452) v1@503.856,-122.25 ; 503.772,-116.75 503.772,-116.641 ; 503.78,-147.865 cw(c503.378,-148.268) 503.947,-148.273 ; 503.803,-153.924 ccw(c503.376,-153.497) 503.98,-153.497 ccw(c504.584,-153.497) 504.157,-153.924 ; 504.272,-143.921 504.272,-146.868 504.488,-147.084 505.035,-147.084 505.523,-147.573 505.523,-150.475 505.758,-150.71 508.603,-150.71 509.06,-151.167 509.06,-154.85 ; 504.272,-130.403 cw(c506.139,-130.403) 504.819,-129.082 ; 504.272,-129.92 cw(c505.657,-129.92) 504.678,-128.941 ; 504.272,-129.64 504.272,-131.621 504.272,-128.878 ; 504.272,-129.437 cw(c505.174,-129.437) 504.536,-128.799 ; 504.311,295.358 ccw(c503.788,295.881) 504.528,295.881 ccw(c505.267,295.881) 504.744,295.358 ; 504.336,298.574 509.001,298.574 ; 504.528,295.103 504.528,296.574 ; 504.605,282.672 ccw(c504.178,283.099) 504.782,283.099 ccw(c505.385,283.099) 504.959,282.672 ; 504.764,-145.449 cw(c504.175,-146.037) 505.007,-146.037 ; 504.772,-131.621 504.772,-130.055 504.996,-129.831 506.139,-129.831 506.291,-129.679 506.291,-128.865 ; 504.782,281.745 504.782,285.428 505.474,286.12 512.332,286.12 512.901,286.689 512.901,292.674 ; 504.855,-145.541 ccw(c505.314,-145.083) 505.314,-145.731 ; 505.073,-153.924 ccw(c504.646,-153.497) 505.25,-153.497 ccw(c505.854,-153.497) 505.427,-153.924 ; 505.351,-119.126 cw(c504.828,-119.649) 505.568,-119.649 cw(c506.307,-119.649) 505.784,-119.126 ; 505.352,-146.037 504.772,-145.458 504.772,-143.921 504.772,-142.271 506.105,-140.938 v1(506.105,-139.091) 506.105,-136.297 506.381,-136.021 507.672,-136.021 510.026,-136.021 510.28,-135.767 510.28,-134.937 510.407,-134.937 ; 505.411,-98.657 ccw(c504.301,-99.766) 504.301,-98.197 ccw(c504.301,-96.628) 505.411,-97.737 ; 505.411,-96.117 ccw(c504.301,-97.226) 504.301,-95.657 ccw(c504.301,-94.088) 505.411,-95.197 ; 505.553,-98.515 ccw(c504.784,-99.283) 504.784,-98.197 ccw(c504.784,-97.111) 505.553,-97.879 ; 505.553,-95.975 ccw(c504.784,-96.743) 504.784,-95.657 ccw(c504.784,-94.571) 505.553,-95.339 ; 505.568,-118.909 505.568,-120.646 505.832,-120.911 508.01,-120.911 508.368,-121.269 508.368,-133.641 ; 505.875,282.672 ccw(c505.448,283.099) 506.052,283.099 ccw(c506.655,283.099) 506.229,282.672 ; v1@505.928,-139.268 cw(c505.502,-139.695) 506.105,-139.695 cw(c506.709,-139.695) v1@506.282,-139.268 ; v1@505.928,-138.914 ccw(c505.502,-138.487) 506.105,-138.487 ccw(c506.709,-138.487) v1@506.282,-138.914 ; 506.052,281.745 506.052,285.174 506.598,285.72 512.821,285.72 513.401,286.3 513.401,292.674 ; 506.075,-129.082 cw(c505.552,-129.605) 506.291,-129.605 cw(c507.031,-129.605) 506.508,-129.082 ; 506.089,331.058 cw(c505.566,330.535) 506.306,330.535 cw(c507.045,330.535) 506.522,331.058 ; 506.261,334.654 v1@506.891,334.654 ; 506.286,295.105 506.356,295.105 ; 506.306,331.275 506.306,330.517 506.653,330.17 508.658,330.17 508.932,329.897 508.932,312.871 508.932,312.827 509.193,312.566 515.178,312.566 515.901,311.844 515.901,304.974 ; 506.306,332.926 v1(507.068,332.926) ; 506.343,-153.924 ccw(c505.916,-153.497) 506.52,-153.497 ccw(c507.124,-153.497) 506.697,-153.924 ; 506.356,293.454 507.093,293.454 ; 506.358,-145.313 cw(c505.633,-146.037) 506.658,-146.037 ; v1@506.436,-133.299 ccw(c506.01,-133.726) 506.01,-133.122 ccw(c506.01,-132.518) v1@506.436,-132.945 ; 506.549,334.477 cw(c506.891,334.236) v1@506.891,334.654 ; 506.549,334.831 ccw(c506.891,335.073) v1@506.891,334.654 ; 506.564,332.713 cw(c507.068,332.224) v1(507.068,332.926) ; 506.564,333.139 ccw(c507.068,333.628) v1(507.068,332.926) ; 506.573,293.238 cw(c507.093,292.72) 507.093,293.454 ; 506.573,293.671 ccw(c507.093,294.189) 507.093,293.454 ; 506.643,-145.598 ccw(c506.965,-145.276) 506.965,-145.731 ; 506.699,-145.654 cw(c506.316,-146.037) 506.858,-146.037 ; 506.74,-145.695 506.232,-145.187 505.47,-145.187 505.272,-144.989 505.272,-143.921 505.272,-142.337 506.088,-141.521 507.672,-141.521 507.104,-141.521 ; v1@506.841,334.477 ccw(c506.414,334.051) 506.414,334.654 ccw(c506.414,335.258) v1@506.841,334.831 ; v1@506.891,332.749 ccw(c506.464,332.323) 506.464,332.926 ccw(c506.464,333.53) v1@506.891,333.103 ; 507.145,282.672 ccw(c506.718,283.099) 507.322,283.099 ccw(c507.925,283.099) 507.499,282.672 ; 507.15,342.678 cw(c507.15,341.08) 508.28,342.21 cw(c509.41,343.34) 507.812,343.34 ; 507.15,342.878 cw(c507.15,341.763) 507.938,342.551 cw(c508.727,343.34) 507.612,343.34 ; 507.15,343.34 508.431,342.059 508.431,338.271 508.704,337.998 512.114,337.998 512.452,337.66 512.452,336.79 512.749,336.493 525.957,336.493 526.338,336.112 526.338,323.031 526.846,322.523 526.846,322.079 ; 507.322,281.745 507.322,284.666 507.976,285.32 513.183,285.32 513.901,286.038 513.901,292.674 ; v1@507.379,-133.122 ccw(c506.776,-133.122) 507.202,-132.695 ccw(c507.629,-132.268) v1@507.629,-132.872 ; v1@507.415,355.035 510.463,355.035 511.079,355.035 511.333,355.289 511.333,363.811 511.987,364.465 513.932,364.465 ; v1@507.542,295.574 509.001,295.574 ; 507.613,-153.924 ccw(c507.186,-153.497) 507.79,-153.497 ccw(c508.394,-153.497) 507.967,-153.924 ; 507.672,-139.521 510.622,-139.521 512.045,-140.944 512.362,-140.944 512.426,-140.944 513.124,-140.245 516.045,-140.245 516.37,-140.57 ; 507.672,-139.021 512.091,-139.021 ; 507.672,-138.521 511.731,-138.521 513.782,-136.471 513.782,-132.018 514.515,-131.285 ; 507.672,-138.021 511.666,-138.021 513.382,-136.305 513.382,-130.074 513.763,-129.693 515.63,-129.693 515.903,-129.42 515.903,-121.311 516.157,-121.057 520.71,-121.057 521.103,-120.665 521.103,-118.864 ; 507.672,-137.521 511.6,-137.521 512.982,-136.139 512.982,-129.82 513.509,-129.293 515.249,-129.293 515.503,-129.039 515.503,-117.755 516.045,-117.213 ; 507.672,-137.021 511.534,-137.021 512.582,-135.974 512.582,-129.185 512.874,-128.893 514.741,-128.893 515.103,-128.531 515.103,-117.139 515.884,-116.358 v1(515.884,-116.104) ; 507.672,-136.521 511.469,-136.521 512.182,-135.808 512.182,-128.95 512.816,-128.316 512.816,-125.031 ; 507.672,-135.521 509.46,-135.521 509.701,-135.281 509.701,-133.992 510.407,-133.286 ; 507.672,-135.021 508.905,-135.021 509.301,-134.626 509.301,-126.285 509.282,-126.266 509.282,-121.908 509.859,-121.33 513.706,-121.33 514.595,-120.441 514.595,-116.059 514.614,-116.04 ; 507.672,-134.521 508.481,-134.521 508.776,-134.227 508.776,-133.513 508.772,-133.509 508.772,-121.565 509.534,-120.803 512.836,-120.803 513.217,-120.422 513.217,-116.04 ; 507.672,-134.021 507.988,-134.021 508.368,-133.641 ; v1(507.923,354.273) 508.177,354.527 510.209,354.527 511.479,354.527 511.733,354.781 511.733,355.416 511.733,362.02 512.178,362.465 513.932,362.465 ; 508.018,294.932 cw(c508.336,294.614) 508.336,295.064 ; 508.071,294.986 cw(c508.275,294.782) 508.334,295.064 ; 508.337,-134.511 ccw(c508.337,-134.139) 508.6,-134.402 ; 508.345,-134.015 cw(c508.568,-133.841) 508.368,-133.641 ; 508.415,282.672 ccw(c507.988,283.099) 508.592,283.099 ccw(c509.195,283.099) 508.769,282.672 ; v1@508.558,353.638 511.098,353.638 511.987,353.638 512.241,353.892 512.241,356.211 512.495,356.465 ; 508.592,281.745 508.592,284.412 509.1,284.92 513.672,284.92 514.401,285.649 514.401,292.674 ; v1@508.735,353.462 cw(c509.161,353.035) 509.161,353.638 cw(c509.161,354.242) v1@508.735,353.815 ; 508.883,-153.924 ccw(c508.456,-153.497) 509.06,-153.497 ccw(c509.664,-153.497) 509.237,-153.924 ; 509.001,295.074 508.159,295.074 507.449,294.363 507.449,293.81 507.093,293.454 ; 509.001,296.074 518.396,296.074 518.684,296.361 518.684,303.185 519.622,304.123 520.608,304.123 v1(521.258,303.473) ; 509.001,296.574 504.528,296.574 ; 509.001,297.074 497.84,297.074 497.543,296.776 497.543,294.202 ; 509.001,301.074 505.646,301.074 504.932,301.788 504.932,302.578 504.93,302.58 504.93,304.113 504.932,304.115 504.932,325.385 504.745,325.571 496.65,325.571 496.635,325.556 495.619,325.556 495.35,325.825 ; 509.001,302.074 506.043,302.074 505.732,302.385 505.732,302.91 505.73,302.912 505.73,303.781 505.732,303.783 505.732,326.274 505.036,326.97 493.259,326.97 492.71,327.519 492.71,346.68 493.191,347.161 528.751,347.161 529.259,347.669 529.259,355.797 529.927,356.465 531.632,356.465 ; 509.001,302.574 506.409,302.574 506.132,302.851 506.132,303.075 506.13,303.077 506.13,303.616 506.132,303.618 506.132,326.782 505.544,327.37 493.424,327.37 493.11,327.685 493.11,345.175 ; 509.222,340.332 cw(c508.092,339.202) 509.69,339.202 cw(c511.288,339.202) 510.158,340.332 ; 509.363,340.473 cw(c508.574,339.685) 509.69,339.685 cw(c510.805,339.685) 510.016,340.473 ; 509.511,331.058 cw(c508.988,330.535) 509.728,330.535 cw(c510.468,330.535) 509.945,331.058 ; 509.544,306.624 cw(c509.02,306.101) 509.76,306.101 cw(c510.5,306.101) 509.977,306.624 ; 509.685,282.672 ccw(c509.258,283.099) 509.862,283.099 ccw(c510.465,283.099) 510.039,282.672 ; 509.69,340.8 509.69,338.664 509.955,338.398 512.374,338.398 512.856,337.916 512.856,337.167 513.13,336.893 526.319,336.893 526.738,336.474 526.738,335.731 526.738,323.393 526.973,323.158 527.862,323.158 528.243,322.777 528.243,322.079 ; 509.69,342.678 cw(c509.69,341.08) 510.82,342.21 cw(c511.95,343.34) 510.352,343.34 ; 509.69,342.878 cw(c509.69,341.763) 510.478,342.551 cw(c511.267,343.34) 510.152,343.34 ; 509.69,343.34 510.844,342.186 510.844,339.052 511.098,338.798 512.54,338.798 512.94,338.398 519.499,338.398 ; 509.728,331.275 509.728,330.297 509.332,329.901 509.332,313.379 509.332,313.335 509.701,312.966 515.448,312.966 516.401,312.014 516.401,304.974 ; 509.728,332.926 510.072,332.926 509.735,332.926 ; 509.76,306.841 509.76,306.081 510.082,305.759 511.225,305.759 ; 509.819,-133.874 cw(c510.407,-134.462) 510.407,-133.63 ; 509.862,281.745 509.862,283.777 510.497,284.412 513.926,284.412 514.901,285.387 514.901,292.674 ; 509.911,-133.782 ccw(c509.453,-133.324) 510.101,-133.324 ; 509.953,322.325 ccw(c509.407,322.871) 510.179,322.871 ; 509.963,323.635 cw(c509.44,323.112) 510.179,323.112 cw(c510.919,323.112) 510.396,323.635 ; 510.179,322.156 510.179,323.852 ; 510.179,322.826 ccw(c510.887,322.826) 510.386,322.325 ; 510.19,-135.192 cw(c509.974,-135.408) 510.28,-135.408 cw(c510.69,-135.407) 510.465,-135.064 ; 510.28,-135.777 cw(c510.933,-135.777) 510.575,-135.231 ; 510.792,-123.38 512.816,-123.38 ; 511.059,-139.021 cw(c511.059,-140.558) 512.145,-139.471 ; 511.086,305.759 cw(c511.086,305.324) 511.394,305.632 ; 511.143,-123.631 cw(c511.747,-124.235) 511.747,-123.38 ; 511.143,-123.157 ccw(c511.682,-122.617) 511.682,-123.38 ; 511.232,-140.131 ccw(c512.362,-139.001) 512.362,-140.599 ccw(c512.362,-139.614) 513.059,-140.311 ; 511.284,-123.772 cw(c512.229,-124.718) 512.229,-123.38 ; 511.284,-123.015 ccw(c512.165,-122.134) 512.165,-123.38 ; 511.289,305.695 ccw(c511.401,305.807) 511.401,305.649 ; 511.391,305.636 ccw(c511.225,305.586) 511.225,305.759 ; 511.401,292.674 511.401,294.632 511.733,294.964 518.464,294.964 519.084,295.584 519.084,302.95 519.607,303.473 v1(520.242,303.473) ; 511.401,304.974 511.401,305.584 511.225,305.759 ; 511.41,-111.278 511.727,-111.595 ; 511.411,306.841 511.901,306.351 511.901,304.974 ; 511.461,306.535 cw(c511.484,305.973) 511.882,306.371 cw(c512.215,306.704) 511.751,306.787 ; 511.542,-139.021 cw(c511.542,-140.075) 512.287,-139.33 ; 511.573,-140.473 ccw(c512.362,-139.684) 512.362,-140.799 ccw(c512.362,-140.297) 512.717,-140.652 ; 511.614,320.122 cw(c511.091,319.599) 511.83,319.599 cw(c512.57,319.599) 512.047,320.122 ; 511.83,320.338 511.83,316.353 511.83,313.777 512.228,313.379 516.559,313.379 516.901,313.038 516.901,304.974 ; 511.915,-140.814 ccw(c512.362,-140.367) 512.362,-140.999 ; 512.024,-139.021 cw(c512.024,-139.592) 512.428,-139.189 ; 512.23,340.8 512.23,339.68 512.495,339.414 516.051,339.414 517.575,340.938 519.499,340.938 ; 512.23,342.678 cw(c512.23,341.08) 513.36,342.21 cw(c514.49,343.34) 512.892,343.34 ; 512.23,342.878 cw(c512.23,341.763) 513.018,342.551 cw(c513.807,343.34) 512.692,343.34 ; 512.23,343.34 513.488,342.081 515.486,342.081 516.248,342.843 538.149,342.843 538.676,342.316 538.676,292.062 538.041,291.427 524.853,291.427 524.321,291.959 524.321,295.48 523.727,296.074 521.301,296.074 ; 512.6,-125.286 cw(c512.077,-125.809) 512.816,-125.809 cw(c513.556,-125.809) 513.033,-125.286 ; 512.6,-123.597 ccw(c512.077,-124.12) 512.077,-123.38 ccw(c512.077,-122.641) 512.6,-123.164 ; 512.668,-140.906 cw(c513.163,-140.906) 512.813,-140.556 ; 512.808,-113.663 cw(c512.069,-114.402) 513.111,-114.482 ; 513,-116.434 cw(c512.477,-116.957) 513.217,-116.957 cw(c513.957,-116.957) 513.434,-116.434 ; 513.116,-113.97 cw(c512.64,-114.446) 513.31,-114.497 ; 513.125,-114.198 ccw(c513.085,-114.072) 513.217,-114.072 ; 513.199,356.183 ccw(c512.516,355.5) 512.516,356.465 ; 513.199,356.748 cw(c512.516,357.431) 512.516,356.465 ; 513.199,362.183 ccw(c512.516,361.5) 512.516,362.465 ccw(c512.516,363.431) 513.199,362.748 ; 513.199,364.183 ccw(c512.516,363.5) 512.516,364.465 ccw(c512.516,365.431) 513.199,364.748 ; 513.217,-114.516 513.217,-114.072 ; 513.309,-114.198 cw(c513.349,-114.072) 513.217,-114.072 ; 513.519,317.469 cw(c512.996,316.946) 513.735,316.946 cw(c514.475,316.946) 513.952,317.469 ; 513.735,317.686 513.735,315.441 513.892,315.284 521.258,315.284 521.597,314.946 521.597,305.418 521.153,304.974 518.901,304.974 ; 513.782,-135.292 515.213,-135.292 ; 513.932,356.465 512.516,356.465 ; 514.397,-116.434 cw(c513.92,-116.912) 514.595,-116.912 ; 514.413,-114.258 ccw(c514.031,-113.818) 514.614,-113.818 ; 514.595,-117.002 cw(c515.399,-117.002) 514.831,-116.434 ; 514.614,-114.516 514.614,-113.818 ; 514.77,343.34 538.668,343.34 539.076,342.932 539.076,291.827 538.276,291.027 524.687,291.027 523.832,291.883 523.832,295.207 523.465,295.574 521.301,295.574 ; 514.815,-114.258 cw(c515.197,-113.818) 514.614,-113.818 ; 514.942,340.972 514.77,340.8 516.413,342.443 537.787,342.443 538.276,341.954 538.276,292.228 537.875,291.827 525.018,291.827 524.721,292.125 524.721,295.842 523.989,296.574 521.301,296.574 ; 514.958,-135.509 ccw(c514.435,-136.032) 514.435,-135.292 ccw(c514.435,-134.553) 514.958,-135.076 ; 515.096,343.013 cw(c515.885,342.225) 515.885,343.34 cw(c515.885,344.455) 515.096,343.667 ; 515.238,342.872 cw(c516.368,341.742) 516.368,343.34 cw(c516.368,344.938) 515.238,343.808 ; 515.386,326.83 515.411,326.806 ; 515.401,292.674 515.401,284.947 516.216,284.131 517.381,284.131 517.609,283.904 517.609,281.745 ; 515.408,322.172 515.577,322.004 ; 515.408,323.792 515.411,323.794 ; 515.583,-117.675 cw(c516.358,-118.45) 516.449,-117.358 ; 515.888,-117.37 cw(c516.405,-117.886) 516.465,-117.158 ; 515.901,292.674 515.901,285.209 516.578,284.531 518.505,284.531 518.879,284.158 518.879,281.745 ; 516.164,-117.302 ccw(c516.045,-117.338) 516.045,-117.213 ; 516.164,-117.125 cw(c516.045,-117.089) 516.045,-117.213 ; 516.191,-140.837 ccw(c516.082,-140.57) 516.37,-140.57 ; v1@516.287,-119.97 cw(c515.925,-120.36) 516.457,-120.36 ; 516.37,-141.402 516.37,-140.57 ; 516.401,292.674 516.401,285.598 517.067,284.931 519.883,284.931 520.149,284.666 520.149,281.745 ; v1(516.457,-119.787) 516.457,-120.36 ; 516.457,-117.213 516.045,-117.213 ; 516.549,-140.837 cw(c516.658,-140.57) 516.37,-140.57 ; v1@516.627,-119.97 ccw(c516.989,-120.36) 516.457,-120.36 ; 516.901,292.674 516.901,289.238 517.482,288.657 517.482,288.286 ; 516.902,-135.254 516.864,-135.292 518.649,-135.292 ; 516.902,-133.648 516.902,-133.521 ; 517.027,-88.366 cw(c519.789,-88.366) 517.836,-86.413 ; 517.027,-87.883 cw(c519.306,-87.883) 517.695,-86.271 ; 517.027,-87.4 cw(c518.823,-87.4) 517.553,-86.13 ; 517.027,-86.917 cw(c518.34,-86.917) 517.412,-85.989 ; 517.071,289.067 cw(c516.338,288.334) 517.375,288.325 ; 517.118,-135.509 cw(c517.641,-136.032) 517.641,-135.292 cw(c517.641,-134.553) 517.118,-135.076 ; v1@517.131,314.346 cw(c516.48,313.695) 517.401,313.695 ; 517.159,-86.201 cw(c516.661,-86.29) 517.019,-86.648 cw(c517.357,-86.986) 517.464,-86.52 ; 517.204,-84.326 ccw(c516.87,-84.513) 516.87,-84.13 ; 517.204,-83.934 cw(c516.87,-83.747) 516.87,-84.13 ; 517.27,-82.413 ccw(c516.587,-83.096) 516.587,-82.13 ccw(c516.587,-81.164) 517.27,-81.847 ; 517.27,-80.413 ccw(c516.587,-81.096) 516.587,-80.13 ccw(c516.587,-79.164) 517.27,-79.847 ; v1@517.273,314.487 cw(c516.963,314.178) 517.401,314.178 ; 517.401,292.674 517.401,289.446 517.736,289.111 518.498,289.111 518.752,288.857 518.752,285.739 519.006,285.485 521.108,285.485 521.419,285.174 521.419,281.745 ; 517.401,304.974 v1@517.401,314.43 ; 517.401,314.143 cw(c517.687,314.143) v1@517.485,314.346 ; 517.401,319.845 517.401,319.955 ; 517.409,288.73 cw(c517.006,288.328) 517.575,288.323 ; 517.432,282.672 ccw(c517.005,283.099) 517.609,283.099 ccw(c518.212,283.099) 517.786,282.672 ; 517.901,292.674 517.901,289.727 518.117,289.511 518.663,289.511 519.152,289.023 519.152,286.12 519.387,285.885 522.232,285.885 522.689,285.428 522.689,281.745 ; 517.901,306.193 cw(c519.768,306.193) 518.448,307.513 ; 517.901,306.676 cw(c519.285,306.676) 518.306,307.655 ; 517.901,306.955 517.901,304.974 517.901,307.717 ; 517.901,307.159 cw(c518.803,307.159) 518.165,307.796 ; 518.003,-84.13 516.87,-84.13 ; 518.003,-82.13 516.584,-82.13 516.138,-82.576 516.138,-89.307 515.503,-89.942 479.943,-89.942 479.481,-90.404 479.481,-91.42 ; 518.392,291.146 cw(c517.804,290.558) 518.636,290.558 ; 518.394,-135.509 ccw(c517.871,-136.032) 517.871,-135.292 ccw(c517.871,-134.553) 518.394,-135.076 ; 518.401,304.974 518.401,306.54 518.625,306.764 519.768,306.764 519.92,306.916 519.92,307.73 ; 518.484,291.054 ccw(c518.942,291.512) 518.942,290.864 ; 518.683,-133.757 518.683,-133.698 518.683,-133.571 ; 518.702,282.672 ccw(c518.275,283.099) 518.879,283.099 ccw(c519.482,283.099) 519.056,282.672 ; 518.98,317.469 cw(c518.457,316.946) 519.196,316.946 cw(c519.936,316.946) 519.413,317.469 ; 518.98,290.558 518.401,291.138 518.401,292.674 518.401,294.324 519.734,295.657 v1(519.734,297.504) 519.734,300.298 520.009,300.574 521.301,300.574 523.655,300.574 523.909,300.828 523.909,301.659 524.036,301.659 ; 519.04,337.939 ccw(c517.93,336.829) 517.93,338.398 ccw(c517.93,339.968) 519.04,338.858 ; 519.04,340.479 ccw(c517.93,339.369) 517.93,340.938 ccw(c517.93,342.508) 519.04,341.398 ; 519.181,338.08 ccw(c518.413,337.312) 518.413,338.398 ccw(c518.413,339.485) 519.181,338.717 ; 519.181,340.62 ccw(c518.413,339.852) 518.413,340.938 ccw(c518.413,342.025) 519.181,341.257 ; 519.196,317.686 519.196,315.949 519.461,315.684 521.639,315.684 521.997,315.327 521.997,302.954 ; 519.337,-119.119 cw(c518.814,-119.642) 519.554,-119.642 cw(c520.294,-119.642) 519.771,-119.119 ; 519.554,-118.864 519.554,-120.181 519.186,-120.549 516.646,-120.549 516.457,-120.36 ; v1@519.557,297.328 cw(c519.13,296.901) 519.734,296.901 cw(c520.337,296.901) v1@519.911,297.328 ; v1@519.557,297.681 ccw(c519.13,298.108) 519.734,298.108 ccw(c520.337,298.108) v1@519.911,297.681 ; 519.704,307.513 cw(c519.18,306.99) 519.92,306.99 cw(c520.66,306.99) 520.137,307.513 ; 519.972,282.672 ccw(c519.545,283.099) 520.149,283.099 ccw(c520.752,283.099) 520.326,282.672 ; 519.987,291.283 cw(c519.262,290.558) 520.287,290.558 ; v1@520.065,303.297 ccw(c519.638,302.87) 519.638,303.473 ccw(c519.638,304.077) v1@520.065,303.65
